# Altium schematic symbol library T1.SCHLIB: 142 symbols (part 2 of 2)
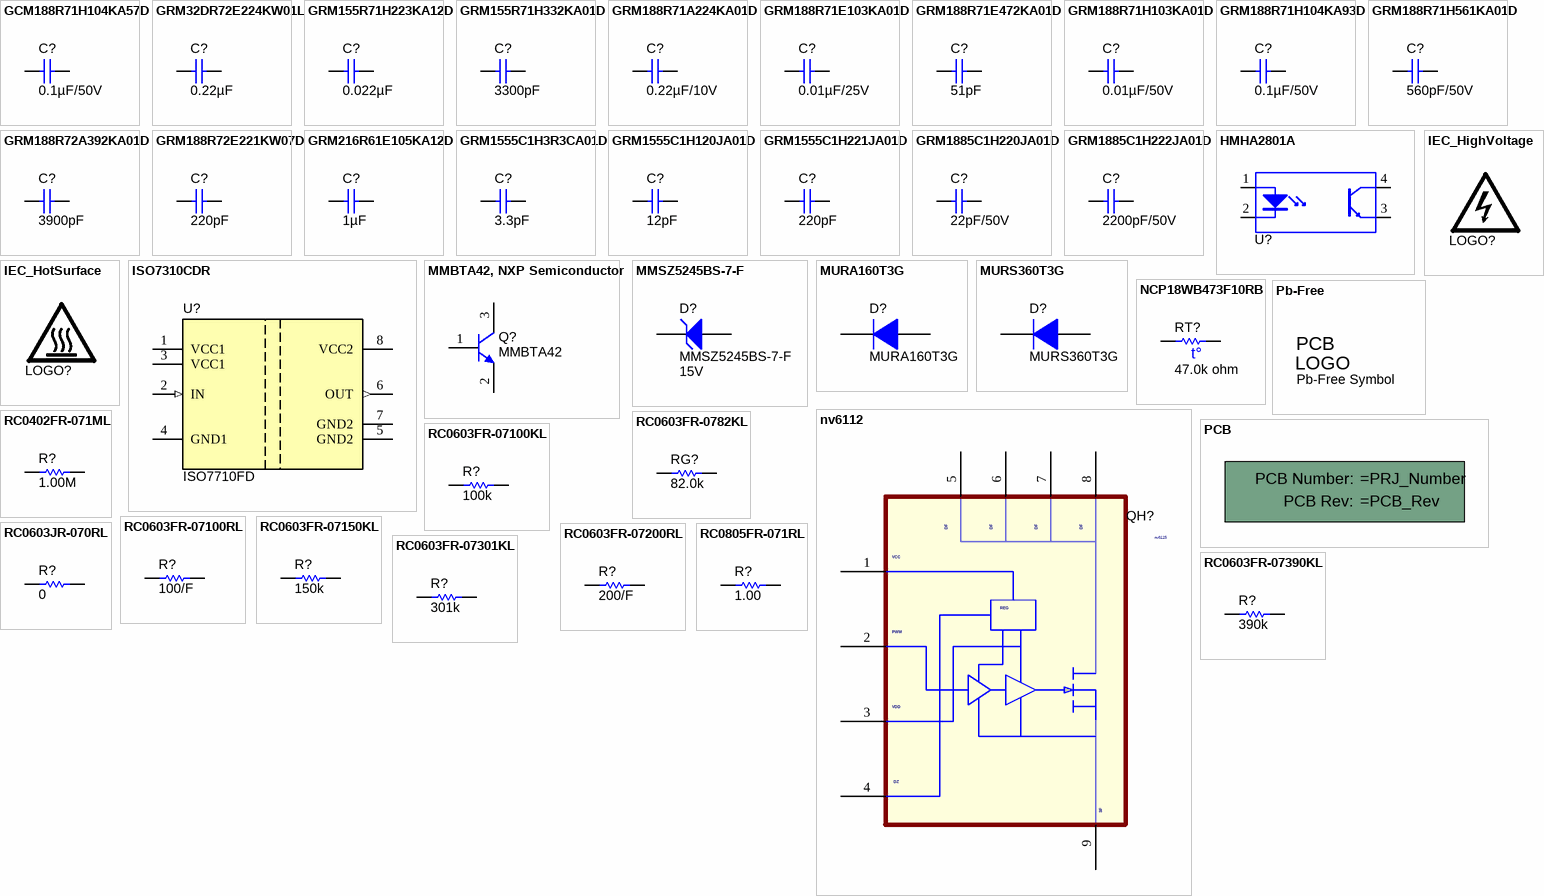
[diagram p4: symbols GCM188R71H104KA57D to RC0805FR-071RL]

## GRM1885C1H222JA01D
designator C?  ValueDisplayed: 2200pF/50V  (hidden comment: GRM1885C1H222JA01D)
CAP, CERM, 2200 pF, 50 V, +/- 5%, C0G/NP0, 0603; Manufacturer: MuRata; Polarized: N; CompType: Capacitor; Value: 2200pF; U/M: EA; Cap_F: 0.0000000022; Tolerance_%: 5; Value1: Unknown; VDC_V: 50; Value2: 50V; TaMin_C: -55; TaMax_C: 125; Cap_Case: 0603; SizeArea_mm2: 1.28; SizeAreaWB_mm2: 4.68; SizeX_mm: 1.6; SizeY_mm: 0.8; SizeZ_mm: 1; AEC Category: Q200
signal-integrity model Cap
simulation model Cap
footprint 0603
footprint 0603M
footprint 0603L
footprint 0603_HV
footprint 0603S
pins: 1, 2

## HMHA2801A
designator U?  (value not drawn)
Optocoupler, 3.75 kV, 80-160% CTR, SMT; Manufacturer: Fairchild Semiconductor; CTR (Min): 80%; CTR (Max): 160%; Voltage_Isolation_Vrms: 3750V; SizeAreaWB_mm2: 4; SizeArea_mm2: 1
footprint MFP04A
pins: 1 A, 2 K, 3 E, 4 C
1 alternate drawing of the same symbol

## IEC_HighVoltage
designator LOGO?, comment DANGER HIGH VOLTAGE  (value not drawn)  (no BOM)
IEC 61010-1 High Voltage Warning; SymbolCreator: a0412235
footprint IEC_HighVoltage_Large
footprint IEC_HighVoltage_Medium
footprint IEC_HighVoltage_Small

## IEC_HotSurface
designator LOGO?, comment CAUTION HOT SURFACE  (value not drawn)  (no BOM)
IEC 61010-1 Hot Surface Warning; SymbolCreator: a0412235
footprint IEC_HotSurface_Large
footprint IEC_HotSurface_Medium
footprint IEC_HotSurface_Small

## ISO7310CDR
designator U?, comment ISO7710FD
Robust EMC, Low Power, Single Channel Digital Isolator, D0008A (SOIC-8); Alternate PartNumber: ISO7310CD; Manufacturer: Texas Instruments; SymbolCreator: a0411947; SizeArea_mm2: 30.38; SizeAreaWB_mm2: 56.58; SizeX_mm: 4.9; SizeY_mm: 6.2; SizeZ_mm: 1.75; CompType: IC; U/M: EA
footprint D0008A_N
footprint D0008A_M
footprint D0008A_L
pins: 1 VCC1 (power), 2 IN (in), 3 VCC1 (power), 4 GND1 (power), 5 GND2 (power), 6 OUT (out), 7 GND2 (power), 8 VCC2 (power)

## MMBTA42, NXP Semiconductor
designator Q?, comment MMBTA42
Transistor, NPN, 300 V, 0.1 A, SOT-23; Manufacturer: NXP Semiconductor; CompType: BJT; PNP: 0; NPN: 1; Vceo_V: 300; Vcesat1_V: 0.5; Value: 300 V; IcRated_A: 0.1; Value1: 0.1 A; TaMin_C: -65; TaMax_C: 150; U/M: EA; AEC Category: Q101
footprint SOT-23
footprint SOT-23M
footprint SOT-23L
pins: 1 B, 2 E, 3 C

## MMSZ5245BS-7-F
designator D?  value 15V
Diode, Zener, 15 V, 200 mW, SOD-323; Manufacturer: Diodes Inc.; SymbolCreator: a0412235; U/M: EA; Power_W: 0.2; Vz_V: 15; Value1: 0.2W; RJA_CperW: 350; SizeAreaWB_mm2: 8.695; SizeArea_mm2: 3.645; SizeX_mm: 2.7; SizeY_mm: 1.35; SizeZ_mm: 1; AEC Category: Q101
signal-integrity model Diode
footprint SOD-323
pins: 1 K, 2 A

## MURA160T3G
designator D?
Diode, Ultrafast, 600V, 1A, SMA; Manufacturer: ON Semiconductor; Value: 1.05V; U/M: EA; Vf_V: 1.05; Io_A: 1; Vr_V: 600; TJmax_C: 175
signal-integrity model Diode
simulation model Dmura160t3
footprint SMA
footprint SMA (Molded Diode, 2-Leads, Body 4.3x2.6mm, IPC Medium Density, based on OnSemi component dimensions and land pattern)
pins: 1 K, 2 A

## MURS360T3G
designator D?
Diode, Ultrafast, 600 V, 3 A, SMC; Manufacturer: ON Semiconductor; U/M: EA; Vf_V: 1.25; Value: 600V; Value1: 3A; Value2: 1.25V; Io_A: 3; Vr_V: 600; TJmax_C: 175; RJC_CperW: 11; SizeAreaWB_mm2: 83.2686; SizeArea_mm2: 50.5686; SizeX_mm: 8.13; SizeY_mm: 6.22; SizeZ_mm: 2.6; AEC Category: Q101
signal-integrity model Diode
simulation model MURS360T3
footprint SMC
pins: 1 K, 2 A

## NCP18WB473F10RB
designator RT?  value 47.0k ohm  (hidden comment: NCP18WB473F10RB)
Thermistor NTC, 47.0k ohm, 1%, 0603; Manufacturer: MuRata; Tolerance_%: 1; Power_W: 0.1; TaMin_C: -40; TaMax_C: 125; U/M: EA
footprint 0603
footprint 0603M
footprint 0603L
footprint 0603_HV
footprint 0603S
pins: 1, 2

## nv6112
designator QH?, comment nv6115
MosFET,DPAK,30V,100A,4.5mohms; Manufacturer 1: International Rectifier; Part Number 1: IRLR7833; Altium-Right: 160; Altium-Bottom: 219
footprint QFN5X6B
pins: 1 VCC, 2 PWM, 3 VDD, 4 DZ, 5 Drain1, 6 Drain2, 7 Drain3, 8 Drain4, 9 S

## Pb-Free
designator Logo?, comment Pb-Free Symbol  (no BOM)
SymbolCreator: a0412235
footprint Pb-Free_Overlay_Medium
footprint Pb-Free_Overlay_Small

## PCB
designator !PCB?, comment Printed Circuit Board  (value not drawn)  (mechanical)
Manufacturer: Any; SymbolCreator: a0412235; CompType: PCB
1 alternate drawing of the same symbol

## RC0402FR-071ML
designator R?  ValueDisplayed: 1.00M  (hidden comment: RC0402FR-071ML)
RES, 1.00 M, 1%, 0.063 W, 0402; Manufacturer: Yageo America; CompType: Resistor; Value: 1.00Meg; Res_ohm: 1000000; Value_Code: 1M00; Tolerance_%: 1; Power_W: 0.063; Value2: 0.063W; TempCo: 100 ppm/C; SizeArea_mm2: 0.5; SizeZ_mm: 0.6; EIA_Code: E96; U/M: EA; AEC Category: Q200
signal-integrity model Resistor
simulation model Resistor
footprint 0402
footprint 0402M
footprint 0402L
footprint 0402S
pins: 1, 2

## RC0603FR-0782KL
designator RG?  ValueDisplayed: 82.0k  (hidden comment: RC0603FR-0782KL)
RES, 82.0 k, 1%, 0.1 W, 0603; Manufacturer: Yageo America; CompType: Resistor; Value: 82.0k; Res_ohm: 82000; Value_Code: 82k0; Tolerance_%: 1; Power_W: 0.1; Value2: 0.1W; VDC_V: 150; TempCo: 200 ppm/C; SizeArea_mm2: 1.28; SizeX_mm: 1.6; SizeY_mm: 0.8; U/M: EA; AEC Category: Q200; Green_Lifecycle: Active; Green_REACh: Passed
signal-integrity model Resistor
simulation model Resistor
footprint 0603
footprint 0603M
footprint 0603L
footprint 0603_HV
footprint 0603S
pins: 1, 2

## RC0603FR-07100KL
designator R?  ValueDisplayed: 100k  (hidden comment: RC0603FR-07100KL)
RES, 100 k, 1%, 0.1 W, 0603; Manufacturer: Yageo America; CompType: Resistor; Value: 100k; Res_ohm: 100000; Tolerance_%: 1; Power_W: 0.1; Value2: 0.1W; VDC_V: 150; TempCo: 200 ppm/C; SizeArea_mm2: 1.28; SizeX_mm: 1.6; SizeY_mm: 0.8; EIA_Code: E96; U/M: EA; AEC Category: Q200
signal-integrity model Resistor
simulation model Resistor
footprint 0603
footprint 0603M
footprint 0603L
footprint 0603_HV
footprint 0603S
pins: 1, 2

## RC0603FR-07100RL
designator R?  ValueDisplayed: 100/F  (hidden comment: RC0603FR-07100RL)
RES, 100, 1%, 0.1 W, 0603; Manufacturer: Yageo America; CompType: Resistor; Value: 100; Value_Code: 100R; Tolerance_%: 1; Power_W: 0.1; Value2: 0.1W; VDC_V: 150; TempCo: 200 ppm/C; SizeArea_mm2: 1.28; SizeX_mm: 1.6; SizeY_mm: 0.8; EIA_Code: E96; U/M: EA; AEC Category: Q200
signal-integrity model Resistor
simulation model Resistor
footprint 0603
footprint 0603M
footprint 0603L
footprint 0603_HV
footprint 0603S
pins: 1, 2

## RC0603FR-07150KL
designator R?  ValueDisplayed: 150k  (hidden comment: RC0603FR-07150KL)
RES, 150 k, 1%, 0.1 W, 0603; Manufacturer: Yageo America; CompType: Resistor; Value: 150k; Res_ohm: 150000; Tolerance_%: 1; Power_W: 0.1; Value2: 0.1W; VDC_V: 150; TempCo: 200 ppm/C; SizeArea_mm2: 1.28; SizeX_mm: 1.6; SizeY_mm: 0.8; EIA_Code: E96; U/M: EA; AEC Category: Q200
signal-integrity model Resistor
simulation model Resistor
footprint 0603
footprint 0603M
footprint 0603L
footprint 0603_HV
footprint 0603S
pins: 1, 2

## RC0603FR-07200RL
designator R?  ValueDisplayed: 200/F  (hidden comment: RC0603FR-07200RL)
RES, 200, 1%, 0.1 W, 0603; Manufacturer: Yageo America; CompType: Resistor; Value: 200; Value_Code: 200R; Tolerance_%: 1; Power_W: 0.1; Value2: 0.1W; VDC_V: 150; TempCo: 200 ppm/C; SizeArea_mm2: 1.28; SizeX_mm: 1.6; SizeY_mm: 0.8; EIA_Code: E96; U/M: EA; AEC Category: Q200
signal-integrity model Resistor
simulation model Resistor
footprint 0603
footprint 0603M
footprint 0603L
footprint 0603_HV
footprint 0603S
pins: 1, 2

## RC0603FR-07301KL
designator R?  ValueDisplayed: 301k  (hidden comment: RC0603FR-07301KL)
RES, 301 k, 1%, 0.1 W, 0603; Manufacturer: Yageo America; CompType: Resistor; Value: 301k; Res_ohm: 301000; Tolerance_%: 1; Power_W: 0.1; Value2: 0.1W; VDC_V: 150; TempCo: 200 ppm/C; SizeArea_mm2: 1.28; SizeX_mm: 1.6; SizeY_mm: 0.8; EIA_Code: E96; U/M: EA; AEC Category: Q200
signal-integrity model Resistor
simulation model Resistor
footprint 0603
footprint 0603M
footprint 0603L
footprint 0603_HV
footprint 0603S
pins: 1, 2

## RC0603FR-07390KL
designator R?  ValueDisplayed: 390k  (hidden comment: RC0603FR-07390KL)
RES, 390 k, 1%, 0.1 W, 0603; Manufacturer: Yageo America; CompType: Resistor; Value: 390k; Res_ohm: 390000; Tolerance_%: 1; Power_W: 0.1; Value2: 0.1W; VDC_V: 150; TempCo: 200 ppm/C; SizeArea_mm2: 1.28; SizeX_mm: 1.6; SizeY_mm: 0.8; U/M: EA; AEC Category: Q200
signal-integrity model Resistor
simulation model Resistor
footprint 0603
footprint 0603M
footprint 0603L
footprint 0603_HV
footprint 0603S
pins: 1, 2

## RC0603JR-070RL
designator R?  ValueDisplayed: 0  (hidden comment: RC0603JR-070RL)
RES, 0, 5%, 0.1 W, 0603; Manufacturer: Yageo America; CompType: Resistor; Value: 0; Value_Code: 0000; Tolerance_%: 5; Power_W: 0.1; Value2: 0.1W; VDC_V: 50; TempCo: 200 ppm/C; SizeArea_mm2: 1.28; SizeX_mm: 1.6; SizeY_mm: 0.8; SizeZ_mm: 1; EIA_Code: E24; U/M: EA; AEC Category: Q200
signal-integrity model Resistor
simulation model Resistor
footprint 0603
footprint 0603M
footprint 0603L
footprint 0603_HV
footprint 0603S
pins: 1, 2

## RC0805FR-071RL
designator R?  ValueDisplayed: 1.00  (hidden comment: RC0805FR-071RL)
RES, 1.00, 1%, 0.125 W, 0805; Manufacturer: Yageo America; CompType: Resistor; Value: 1.00; Res_ohm: 1; Value_Code: 1R00; Power_W: 0.125; Value2: 0.125W; VDC_V: 150; TempCo: 200 ppm/C; SizeArea_mm2: 2.5; SizeX_mm: 2; SizeY_mm: 1.25; SizeZ_mm: 1.45; EIA_Code: E96; U/M: EA; AEC Category: Q200
signal-integrity model Resistor
simulation model Resistor
footprint 0805_HV
footprint 0805_HV1
footprint 0805
footprint 0805M
footprint 0805L
pins: 1, 2

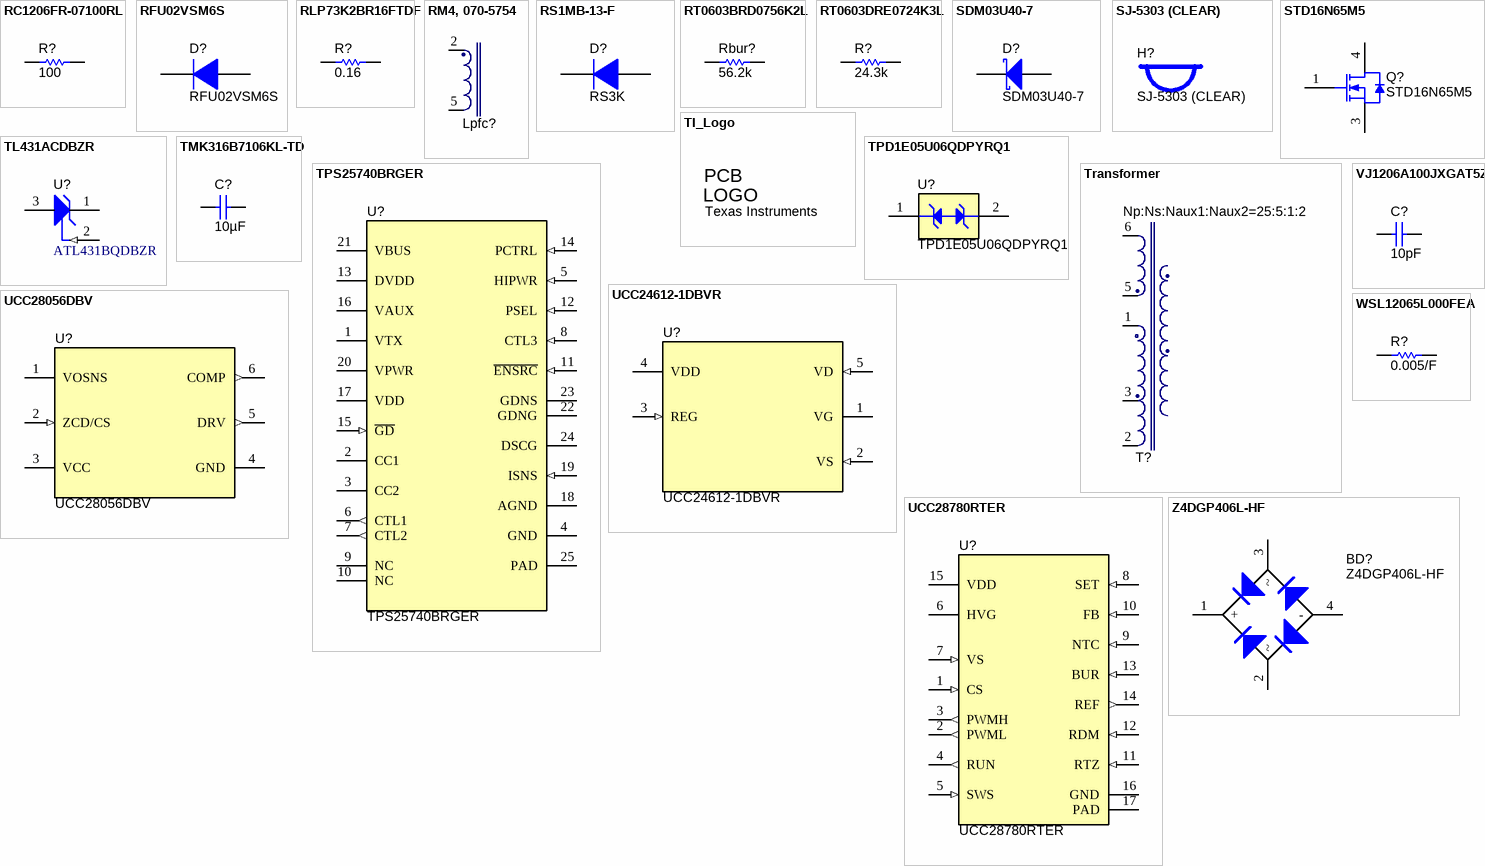
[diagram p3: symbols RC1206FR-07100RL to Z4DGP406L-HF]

## RC1206FR-07100RL
designator R?  ValueDisplayed: 100  (hidden comment: RC1206FR-07100RL)
RES, 100, 1%, 0.25 W, 1206; Manufacturer: Yageo America; CompType: Resistor; Value: 100; Value_Code: 100R; Tolerance_%: 1; Power_W: 0.25; Value2: 0.25W; VDC_V: 200; TempCo: 100 ppm/C; SizeArea_mm2: 5.12; SizeX_mm: 3.2; SizeY_mm: 1.6; SizeZ_mm: 1.35; EIA_Code: E96; U/M: EA; AEC Category: Q200
signal-integrity model Resistor
simulation model Resistor
footprint 1206
footprint 1206M
footprint 1206L
pins: 1, 2

## RFU02VSM6S
designator D?
Diode, Superfast Rectifier, 600 V, 0.2A; Manufacturer: Comchip Technology; U/M: EA; Vf_V: 1.7; Value: 600V; Value1: 1A; Value2: 1.7V; Io_A: 1; Vr_V: 600; TJmax_C: 150; SizeAreaWB_mm2: 11.7; SizeArea_mm2: 5.6; SizeX_mm: 3.5; SizeY_mm: 1.6; AEC Category: Q101; AEC Qualified: N
footprint RFU02VSM6S (On Semi recommended land pattern)
pins: 1 K, 2 A

## RLP73K2BR16FTDF
designator R?  ValueDisplayed: 0.16  (hidden comment: RLP73K2BR16FTDF)
RES, 0.16, 1%, 0.5 W, 1206; Manufacturer: TE Connectivity; CompType: Resistor; Value: 0.16; Value_Code: R160; Tolerance_%: 1; Power_W: 0.5; Value2: 0.5W; TempCo: 200 ppm/C; SizeArea_mm2: 5.12; SizeX_mm: 3.2; SizeY_mm: 1.6; SizeZ_mm: 1.35; EIA_Code: E96; U/M: EA; AEC Category: Q200; AEC Qualified: N
signal-integrity model Resistor
simulation model Resistor
footprint 1206
footprint 1206M
footprint 1206L
pins: 1, 2

## RM4, 070-5754
designator Lpfc?, comment 070-5754  (value not drawn)
Transformer 6-Terminal , THT, Vertical, RM Style Bobbins, RM4; Manufacturer: Würth Elektronik Midcom; Core: 150-2620
footprint RM4_5754 (THT, Body 11.44x11.44mm, 6Pin, Pitch 2.54mm)
pins: 2, 5

## RS1MB-13-F
designator D?, comment RS3K
Diode, P-N, 1000 V, 1 A, SMB; PartNumber: RS1MB-13-F; Manufacturer: Diodes Inc.; U/M: EA; Vf_V: 1.3; Value: 1000V; Value1: 1A; Value2: 1.3V; Io_A: 1; Vr_V: 1000; TJmax_C: 150; RJC_CperW: 20; SizeAreaWB_mm2: 44.156; SizeArea_mm2: 21.336; SizeX_mm: 5.6; SizeY_mm: 3.81; SizeZ_mm: 2.6; AEC Category: Q101
signal-integrity model Diode
footprint SMB
pins: 1 K, 2 A

## RT0603BRD0756K2L
designator Rbur?  ValueDisplayed: 56.2k  (hidden comment: RT0603BRD0756K2L)
RES, 56.2 k, 0.1%, 0.1 W, 0603; Manufacturer: Yageo America; CompType: Resistor; Value: 56.2k; Res_ohm: 56200; Value_Code: 56k2; Tolerance_%: 0.1; Value2: 0.1W; VDC_V: 75; TempCo: 25 ppm/C; SizeArea_mm2: 1.28; SizeX_mm: 1.6; SizeY_mm: 0.8; SizeZ_mm: 1; EIA_Code: E192; U/M: EA; AEC Category: Q200
signal-integrity model Resistor
simulation model Resistor
footprint 0603
footprint 0603M
footprint 0603L
footprint 0603_HV
footprint 0603S
pins: 1, 2

## RT0603DRE0724K3L
designator R?  ValueDisplayed: 24.3k  (hidden comment: RT0603DRE0724K3L)
RES, 24.3 k, 0.5%, 0.1 W, 0603; Manufacturer: Yageo America; CompType: Resistor; Value: 24.3k; Res_ohm: 24300; Value_Code: 24k3; Tolerance_%: 0.5; Power_W: 0.1; Value2: 0.1W; VDC_V: 75; TempCo: 50 ppm/C; SizeArea_mm2: 1.28; SizeX_mm: 1.6; SizeY_mm: 0.8; SizeZ_mm: 1; EIA_Code: E192; U/M: EA; AEC Category: Q200
signal-integrity model Resistor
simulation model Resistor
footprint 0603
footprint 0603M
footprint 0603L
footprint 0603_HV
footprint 0603S
pins: 1, 2

## SDM03U40-7
designator D?
Diode, Schottky, 40 V, 0.03 A, SOD-523; Manufacturer: Diodes Inc.; U/M: EA; Vf_V: 1; Value: 40V; Value1: 0.03A; Value2: 1V; Io_A: 0.03; Vr_V: 40; TJmax_C: 125; SizeAreaWB_mm2: 5.13; SizeArea_mm2: 1.53; SizeX_mm: 1.7; SizeY_mm: 0.9; SizeZ_mm: 0.65; AEC Category: Q101
signal-integrity model Diode
simulation model DI_SDM03U40
footprint SOD-523
pins: 1 K, 2 A

## SJ-5303 (CLEAR)
designator H?
Bumpon, Hemisphere, 0.44 X 0.20, Clear; Manufacturer: 3M; SymbolCreator: a0412235
footprint Bumpon_SJ5003Transparent (3M Hemispherical Bumpon transparent)

## STD16N65M5
designator Q?
MOSFET, N-CH, 650 V, 12 A, DPAK; Manufacturer: STMicroelectronics; Alternate Manufacturer: None; U/M: EA; ChType: N; Value: 650V; VdsMax_V: 650; Value1: ? ohm; Value2: 31 nC; QgTyp_nC: 31; Vgs_V: 25; IdsMax_A: 12; SizeAreaWB_mm2: 101.7114; SizeArea_mm2: 64.8114; SizeX_mm: 9.91; SizeY_mm: 6.54; SizeZ_mm: 2.29; AEC Category: Q101
footprint DPAK
pins: 1 G, 3 S, 4 D

## TI_Logo
designator Logo?, comment Texas Instruments  (no BOM)
Texas Instrument Corporate Signature; SymbolCreator: codlsc
footprint TI_Stacked_SolderMask_Medium
footprint TI_Stacked_SolderMask_Small
footprint TI_Stacked_Overlay_Medium
footprint TI_Stacked_Overlay_Small
footprint TI_Horizontal_SolderMask_Medium
footprint TI_Horizontal_SolderMask_Small
footprint TI_Horizontal_Overlay_Medium
footprint TI_Horizontal_Overlay_Small
footprint TI_Symbol_SolderMask_Small
footprint TI_Symbol_Overlay_Medium
footprint TI_Symbol_Overlay_Small
footprint TI_Symbol_SolderMask_Medium

## TL431ACDBZR
designator U?, comment ATL431BQDBZR
Adjustable Precision Shunt Regulator, 34 ppm / degC, 100 mA, 0 to 70 degC, 3-pin SOT-23 (DBZ), Green (RoHS & no Sb/Br); Manufacturer: Texas Instruments; Alternate PartNumber: Equivalent; Initial Accuracy @ 25/deg C(%): 1; Iout/Iz(Max)(mA): 100; Min Iz for Regulation(uA): 600; Rating: Catalog; SubFamily: Shunt Voltage Reference; Temp Coeff(Typ)(ppm/ degree C): 34; VO Adj(Max)(V): 36; VO Adj(Min)(V): 2.495
footprint DBZ0003A_N (SOT23, 3-Leads, Body 2.92x1.3 mm, Pitch 0.95 mm, IPC Medium Density)
footprint DBZ0003A_L (SOT23, 3-Leads, Body 2.92x1.3 mm, Pitch 0.95 mm, IPC High Density)
footprint DBZ0003A_M (SOT23, 3-Leads, Body 2.92x1.3 mm, Pitch 0.95 mm, IPC Low Density)
pins: 1 CATHODE, 2 REF (in), 3 ANODE

## TMK316B7106KL-TD
designator C?  ValueDisplayed: 10µF  (hidden comment: TMK316B7106KL-TD)
CAP, CERM, 10 µF, 25 V,+/- 10%, X7R, 1206; Manufacturer: Taiyo Yuden; Polarized: N; CompType: Capacitor; Value: 10uF; U/M: EA; Cap_F: 0.00001; Tolerance_%: 10; VDC_V: 25; Value2: 25V; TaMin_C: -55; TaMax_C: 125; Cap_Case: 1206; SizeArea_mm2: 5.12; SizeAreaWB_mm2: 10.92; SizeX_mm: 3.2; SizeY_mm: 1.6; SizeZ_mm: 1.9; AEC Category: Q200; Green_Lifecycle: Not Set; Green_REACh: Incomplete
signal-integrity model Cap
simulation model Cap
footprint 1206_190
footprint 1206_190M
footprint 1206_190L
pins: 1, 2

## TPD1E05U06QDPYRQ1
designator U?
Automotive 1-Channel Ultra-Low-Capacitance IEC ESD Protection Diode, DPY0002A (X1SON-2); Alternate PartNumber: TPD1E05U06QDPYTQ1; Manufacturer: Texas Instruments; SymbolCreator: a0411947; SizeArea_mm2: 0.6; SizeAreaWB_mm2: 3.2; SizeX_mm: 1; SizeZ_mm: 0.45; CompType: IC; U/M: EA
signal-integrity model Diode
footprint DPY0002A
pins: 1 K, 2 A

## TPS25740BRGER
designator U?
USB Type-C and USB PD Source Controller, RGE0024H (VQFN-24); Alternate PartNumber: TPS25740BRGET; Manufacturer: Texas Instruments; SymbolCreator: a0411947; SizeArea_mm2: 16; SizeAreaWB_mm2: 25; SizeX_mm: 4; SizeZ_mm: 1; CompType: IC; U/M: EA
footprint RGE0024H (QFN, 24-Leads, Body 4x4mm, Pitch 0.5mm, Thermal Pad 2.7x2.7mm, TI Recommended)
footprint RGE0024H_NV
pins: 1 VTX (power), 2 CC1, 3 CC2, 4 GND (power), 5 HIPWR (in), 6 CTL1 (out), 7 CTL2 (out), 8 CTL3 (in), 9 NC, 10 NC, 11 ~{ENSRC} (in), 12 PSEL (in), 13 DVDD (power), 14 PCTRL (in), 15 ~{GD} (in), 16 VAUX (power), 17 VDD (power), 18 AGND (power), 19 ISNS (in), 20 VPWR (power), 21 VBUS (power), 22 GDNG (oc), 23 GDNS (oc), 24 DSCG (oc), 25 PAD (power)

## Transformer
designator T?, comment value Np:Ns:Naux1:Naux2=25:5:1:2  (hidden comment: 750315856)
Transformer, 120 uH, SMT; Manufacturer: Wurth Elektronik; SymbolCreator: Altium; Lp: 120; DCR_ohm: 0.24
footprint RM8_6835 (THT, Body 24.64X24.64mm, 10Pin, Pitch 2.54mm)
pins: 1, 2, 3, 5, 6

## UCC24612-1DBVR
designator U?
UCC24612-1DBV, DBV0005A (SOT-23-5); Alternate PartNumber: UCC24612-1DBVT; Manufacturer: Texas Instruments; SymbolCreator: Altium; SizeArea_mm2: 8.12; SizeAreaWB_mm2: 14.82; SizeX_mm: 2.8; SizeY_mm: 2.9; SizeZ_mm: 1.45; CompType: IC; U/M: EA
footprint DBV0005A_N
footprint DBV0005A_M
footprint DBV0005A_L
pins: 1 VG (power), 2 VS (in), 3 REG (in), 4 VDD (power), 5 VD (in)
1 alternate drawing of the same symbol

## UCC28056DBV
designator U?
6-Pin Single-Phase Transition-Mode PFC Controller, DBV0006A (SOT-23-6); Manufacturer: Texas Instruments; SymbolCreator: Altium; SizeArea_mm2: 8.12; SizeAreaWB_mm2: 14.82; SizeX_mm: 2.8; SizeY_mm: 2.9; SizeZ_mm: 1.45; CompType: IC; U/M: EA
footprint DBV0006A_N
footprint DBV0006A_M
footprint DBV0006A_L
pins: 1 VOSNS, 2 ZCD/CS (in), 3 VCC (power), 4 GND (power), 5 DRV (out), 6 COMP (out)

## UCC28780RTER
designator U?
Active-Clamp Flyback Controller, RTE0016C (WQFN-16); Manufacturer: Texas Instruments; SymbolCreator: Altium; SizeArea_mm2: 9; SizeAreaWB_mm2: 16; SizeX_mm: 3; SizeZ_mm: 0.8; CompType: IC; U/M: EA
footprint UCC28780 (Texas Insturments)
footprint RTE0016C_NV
pins: 1 CS (in), 2 PWML (out), 3 PWMH (out), 4 RUN (out), 5 SWS (in), 6 HVG (power), 7 VS (in), 8 SET (in), 9 NTC (in), 10 FB (in), 11 RTZ (in), 12 RDM (in), 13 BUR (in), 14 REF (out), 15 VDD (power), 16 GND (power), 17 PAD (power)

## VJ1206A100JXGAT5Z
designator C?  ValueDisplayed: 10pF  (hidden comment: VJ1206A100JXGAT5Z)
CAP, CERM, 10 pF, 1000 V, +/- 5%, C0G/NP0, 1206; Manufacturer: Vishay-Vitramon; Polarized: N; CompType: Capacitor; Value: 10pF; U/M: EA; Cap_F: 0.00000000001; Tolerance_%: 5; Value1: Unknown; VDC_V: 1000; Value2: 1000V; TaMin_C: -55; TaMax_C: 125; Cap_Case: 1206; SizeArea_mm2: 5.12; SizeAreaWB_mm2: 10.92; SizeX_mm: 3.2; SizeY_mm: 1.6; SizeZ_mm: 1.35; AEC Category: Q200
signal-integrity model Cap
simulation model Cap
footprint 1206
footprint 1206M
footprint 1206L
pins: 1, 2

## WSL12065L000FEA
designator R?  ValueDisplayed: 0.005/F  (hidden comment: WSL12065L000FEA)
RES, 0.005, 1%, 0.25 W, 1206; Manufacturer: Vishay-Dale; CompType: Resistor; Value: 0.005; Value_Code: 5L000; Tolerance_%: 1; Power_W: 0.25; Value2: 0.25W; TempCo: 110 ppm/C; SizeArea_mm2: 5.12; SizeX_mm: 3.2; SizeY_mm: 1.6; SizeZ_mm: 1.35; EIA_Code: E96; U/M: EA; AEC Category: Q200; AEC Qualified: N
signal-integrity model Resistor
simulation model Resistor
footprint 1206
footprint 1206M
footprint 1206L
pins: 1, 2

## Z4DGP406L-HF
designator BD?
Diode, P-N-Bridge, 600 V, 4 A, Z4-D; Manufacturer: Comchip Technology; U/M: EA; Vf_V: 0.95; Value: 600V; Value1: 4A; Value2: 0.95V; Io_A: 4; Vr_V: 600; TJmax_C: 175; SizeAreaWB_mm2: 126.25; SizeArea_mm2: 85.05; SizeX_mm: 10.5; SizeY_mm: 8.1; SizeZ_mm: 1.55; AEC Category: Q101; AEC Qualified: N
footprint Z4-D
pins: 1 +, 2 ~, 3 ~, 4 -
